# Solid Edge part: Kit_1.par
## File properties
Sűrűség: 0,000 kg/m^3
Pontosság: 0,990
Author: bmolnar
Last saved by: bmolnar
Revision: 77
Username: bmolnar
Dokumentum tartalom típus: 0
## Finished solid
Body 1: solid body, 31 faces, 52 edges, 40 vertices.
  Faces by surface: cylinder 12, plane 11, cone 6, torus 2
  Edges by curve: circle 36, line 14, curve on surface 2
Bounding box of the edges (mm; curved faces can reach further): 44.500 x 44.125 x 4.250, from (-22.25, -20.85, 74.75) to (22.25, 23.275, 79).
Cylindrical faces by radius (mm): R1.25 x2, R2.5 x4, R6.27 x1, R6.85 x1, R15.25 x1, R19.175 x1, R20.85 x1, R22.25 x1
Conical faces (half-angle, radius in mm at the cone's reference point): 14 deg R6.135 x1, 14 deg R6.4811 x1, 17 deg R6.135 x1, 45 deg R7.1 x1, 45 deg R14.75 x1, 87 deg R6.1765 x1
Toroidal faces (ring radius, tube radius in mm): R6.8057 r0.2025 x1, R16.05 r0.8 x1
Planar faces by outward normal: +z 7, -z 2, oblique 2
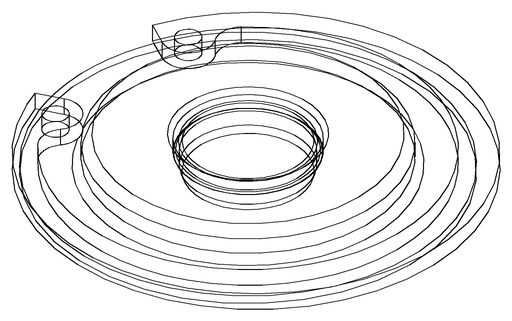
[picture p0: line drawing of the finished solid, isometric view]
